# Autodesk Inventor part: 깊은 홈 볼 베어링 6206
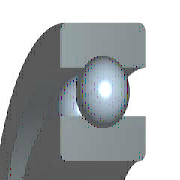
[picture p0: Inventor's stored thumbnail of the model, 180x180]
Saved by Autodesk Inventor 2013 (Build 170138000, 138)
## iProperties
IsCustomPart: 1
Created: 2012-02
Part Number: 깊은 홈 볼 베어링 6206
Material: 강철, 연강
Description: 깊은 그루부 볼 베어링
Document SubType Name: Modeling
Standard: JIS B 1521
Designer: mdu-01
Standards Organization: JIS
Language: ko-KR
Size Designation: 6206 30x62x16
Categories: <MemberInstance><Categories><Category DisplayName="샤프트 부품" InternalName="7f7aeb1f-a693-4053-b835-cee3144e0d98" Mnemonic="SHFT"><Category DisplayName="베어링" Inter
Density: 1 g/cm^3
Author: mdu-01
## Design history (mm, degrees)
sketch "스케치" dims "d0" = 8.32 (= -0.26 x WD + 0.26 x BD)
  geometry: L1 (3.84, 23)-(12.16, 23); L2 (8, 23)-(8, 18.84); L3 (8, 23)-(8, 27.16); L4 (4.909, 20.216)-(0, 20.216); L5 (0, 15)-(16, 15); L6 (4.909, 25.784)-(0, 25.784); L7 (0, 31)-(16, 31); L8 (16, 15)-(16, 20.216); L9 (11.091, 20.216)-(16, 20.216); L10 (11.091, 25.784)-(16, 25.784); L11 (16, 31)-(16, 25.784); L12 (-1.4, 0)-(8.4, 0) reference; L13 (0, -0.3)-(0, 5.3) reference
  constraints: 22 end point, 4 point on line, 2 collinear, 2 perpendicular, 2 symmetric about line, 1 midpoint, 1 parallel, 14 other
  dimensions: "d9" = 30 diameter of L5 L12 (= WD); "d11" = 62 diameter of L7 L12 (= BD); "d12" = 16 distance between parallel lines of L8 L13 (= KB); "d13" = 40.432 diameter of L9 L12 (= 0.326 x BD + 0.674 x WD)
revolve "본체" stored, may be unused: angle "d6" = 90 deg
revolve "볼" stored, may be unused: angle "d7" = 90 deg
pattern_circular "IDS_ARRAYBALL[SIMPL:T]" dims angle "d3" = 360 deg
body "Solid1"
fillet "모깎기1" dims "d1" = 1 (= KRS)
other parameters: "WD" = 30 [user parameter; used in 5 equation terms], "BD" = 62 [user parameter; used in 5 equation terms], "KB" = 16 [user parameter; used in 1 equation term], "KRS" = 1 [user parameter; used in 1 equation term], "d4" = 0, "d5" = 0, "d8" = 0, "d14" = 0, "d15" = 0, "BBA" = 0 [user parameter], "BC0" = 1.12e+07 [user parameter], "BC" = 1.95e+07 [user parameter], "BR" = 31 (= 0.5 x BD) [user parameter], "WR" = 15 (= 0.5 x WD) [user parameter]
